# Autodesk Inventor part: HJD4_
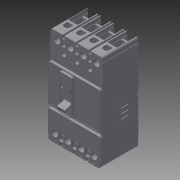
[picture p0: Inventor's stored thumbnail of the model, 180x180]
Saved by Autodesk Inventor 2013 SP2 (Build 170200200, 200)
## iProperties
Created: 2014-08
Part Number: HJD4_
Material: Generic
Document SubType Name: Modeling
Designer: EM/EM
Density: 1 g/cm^3
Description: TYPE HJD THERMAL MAGNETIC CIRCUIT BREAKERS FOUR POLE, SERIES C
MXEDIT: false
MXINVTNRV: INV Versioned Component|HJD4_|004.0
Author: EM/EM
Revision Number: 004
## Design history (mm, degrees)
derived "JD4_.iam"
node "L1"
node "L2"
node "L3"
node "L4"
node "T1"
node "T2"
node "T3"
node "T4"
sketch "Sketch1"
  geometry: C1 r 10.795 at (8.89, 11.913) reference; C2 r 10.795 at (8.89, 11.913); 1 further point
  constraints: 1 centre point, 1 coincident, 1 concentric
extrude "Extrusion1" cut sketch "Sketch1" distance "d1" = 11.1125; taper "d2" = 0 deg
sketch "Sketch2"
  geometry: C1 r 6.35 at (0, 0) reference; C2 r 6.35 at (0, 0); 1 further point
  constraints: 1 centre point, 1 coincident, 1 concentric
extrude "Extrusion2" cut sketch "Sketch2" distance "d3" = 6.35; taper "d5" = 0 deg; dims "d4" = 5.5626, "d6" = 0
sketch "Sketch3"
  geometry: C1 r 10.795 at (11.494, 11.913) reference; C2 r 10.795 at (11.494, 11.913); 1 further point
  constraints: 1 centre point, 1 coincident, 1 concentric
extrude "Extrusion3" cut sketch "Sketch3" distance "d7" = 9.525; taper "d8" = 0 deg
sketch "Sketch4"
  geometry: C1 r 6.35 at (0, 0) reference; C2 r 6.35 at (0, 0); 1 further point
  constraints: 1 centre point, 1 coincident, 1 concentric
extrude "Extrusion4" cut sketch "Sketch4" distance "d9" = 9.525; taper "d11" = 0 deg; dims "d10" = 4.7752, "d12" = 0
sketch "Sketch5"
  geometry: C1 r 10.795 at (11.494, 11.913) reference; C2 r 10.795 at (11.494, 11.913); 1 further point
  constraints: 1 centre point, 1 coincident, 1 concentric
extrude "Extrusion5" cut sketch "Sketch5" distance "d13" = 9.525; taper "d14" = 0 deg
sketch "Sketch6"
  geometry: C1 r 6.35 at (0, 0) reference; C2 r 6.35 at (0, 0); 1 further point
  constraints: 1 centre point, 1 coincident, 1 concentric
extrude "Extrusion6" cut sketch "Sketch6" distance "d15" = 9.525; taper "d17" = 0 deg; dims "d16" = 4.7752, "d18" = 0
sketch "Sketch7"
  geometry: C1 r 10.795 at (11.494, 11.913) reference; C2 r 10.795 at (11.494, 11.913); 1 further point
  constraints: 1 centre point, 1 coincident, 1 concentric
extrude "Extrusion7" cut sketch "Sketch7" distance "d19" = 9.525; taper "d20" = 0 deg
sketch "Sketch8"
  geometry: C1 r 6.35 at (0, 0) reference; C2 r 6.35 at (0, 0); 1 further point
  constraints: 1 centre point, 1 coincident, 1 concentric
extrude "Extrusion8" cut sketch "Sketch8" distance "d21" = 9.525; taper "d23" = 0 deg; dims "d22" = 4.7752, "d24" = 0
sketch "Sketch9"
  geometry: C1 r 8.738 at (0.013, 0) reference; C2 r 8.738 at (0.013, 0); 1 further point
  constraints: 1 centre point, 1 coincident, 1 concentric
extrude "Extrusion9" cut sketch "Sketch9" distance "d25" = 9.525; taper "d27" = 0 deg; dims "d26" = 4.7752, "d28" = 0
sketch "Sketch10"
  geometry: C1 r 8.738 at (-0.013, 0) reference; C2 r 8.763 at (-0.013, 0); 1 further point
  constraints: 1 centre point, 1 coincident
extrude "Extrusion10" cut sketch "Sketch10" distance "d29" = 9.525; taper "d31" = 0 deg; dims "d30" = 4.7752, "d32" = 0
sketch "Sketch11"
  geometry: C1 r 8.738 at (-0.013, 0) reference; C2 r 8.738 at (-0.013, 0); 1 further point
  constraints: 1 centre point, 1 coincident, 1 concentric
extrude "Extrusion11" cut sketch "Sketch11" distance "d33" = 9.525; taper "d35" = 0 deg; dims "d34" = 4.7752, "d36" = 0
sketch "Sketch12"
  geometry: C1 r 8.738 at (-0.038, 0) reference; C2 r 8.738 at (-0.038, 0); 1 further point
  constraints: 1 centre point, 1 coincident, 1 concentric
extrude "Extrusion12" cut sketch "Sketch12" distance "d37" = 9.525; taper "d39" = 0 deg; dims "d38" = 4.7752, "d40" = 0
body "Solid1"
node "JD4_FIX.ipt:1"
node "JD4_FIX2.ipt:1"
body "Solid2"
